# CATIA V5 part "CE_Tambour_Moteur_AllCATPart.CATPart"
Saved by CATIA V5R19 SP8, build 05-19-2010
Part number: CE16_Tambour_Moteur_AllCATPart
Bounding box of the stored display mesh (mm): x -237.5 to 262.51, y 246.141 to 326.11, z 79.516 to 159.484
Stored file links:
  D:\Documents\1_Travail\1 - ac-limoges.fr\ac-limoges.fr\Emmanuel Maynard - STI2D_Turgot\2 -2I2D\1_SEQUENCE_ Tapis_de_course\3- Spécificités\Spé_ITEC\3-Pente\Tapis_TC520B_Pente\CE_Tambour_Moteur_AllCATPart.CATPart
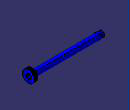
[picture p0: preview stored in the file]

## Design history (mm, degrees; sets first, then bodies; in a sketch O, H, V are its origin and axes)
AxisSystem1: origin (0, 0, 0), X (1, 0, 0), Y (0, 1, 0), Z (0, 0, 1)
Body1 (main body)
  Sketch1 on face of Solid1, origin (262.5, 0, 0), H (0, 1, 0), V (0, 0, 1)
    projected circle E1 centre (287.9309, 92.796) radius 3.3695 from face of Solid2
  Pad1: profile Sketch1, direction (1, 0, 0), length 0.01
Body2 "Tambour_moteur.1"
  Solid1: solid without history
  Body3 "Tambour_moteur.1\\Poulie"
    Solid2 "Solide.1": solid without history
  Add1 "Tambour_moteur.1\\Poulie": tool Body3
  Split1: SplitPlane face of Solid1
Body4 "snr_62202ee_1_1.1"
  Solid3 "Solide.1": solid without history
  Body5 "snr_62202ee_1_1.1\\snr_62202ee_1_2"
    Solid4 "Solide.1": solid without history
  Add2 "snr_62202ee_1_1.1\\snr_62202ee_1_2": tool Body5
  Body6 "snr_62202ee_1_1.1\\snr_62202ee_1_3"
    Solid5 "Solide.1": solid without history
  Add3 "snr_62202ee_1_1.1\\snr_62202ee_1_3": tool Body6
  Body7 "snr_62202ee_1_1.1\\snr_62202ee_1_4"
    Solid6 "Solide.1": solid without history
  Add4 "snr_62202ee_1_1.1\\snr_62202ee_1_4": tool Body7
  Body8 "snr_62202ee_1_1.1\\snr_62202ee_1_5"
    Solid7 "Solide.1": solid without history
  Add5 "snr_62202ee_1_1.1\\snr_62202ee_1_5": tool Body8
Body9 "snr_62202ee_1_1.2"
  Solid8 "Solide.1": solid without history
  Body10 "snr_62202ee_1_1.2\\snr_62202ee_1_2"
    Solid9 "Solide.1": solid without history
  Add6 "snr_62202ee_1_1.2\\snr_62202ee_1_2": tool Body10
  Body11 "snr_62202ee_1_1.2\\snr_62202ee_1_3"
    Solid10 "Solide.1": solid without history
  Add7 "snr_62202ee_1_1.2\\snr_62202ee_1_3": tool Body11
  Body12 "snr_62202ee_1_1.2\\snr_62202ee_1_4"
    Solid11 "Solide.1": solid without history
  Add8 "snr_62202ee_1_1.2\\snr_62202ee_1_4": tool Body12
  Body13 "snr_62202ee_1_1.2\\snr_62202ee_1_5"
    Solid12 "Solide.1": solid without history
  Add9 "snr_62202ee_1_1.2\\snr_62202ee_1_5": tool Body13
